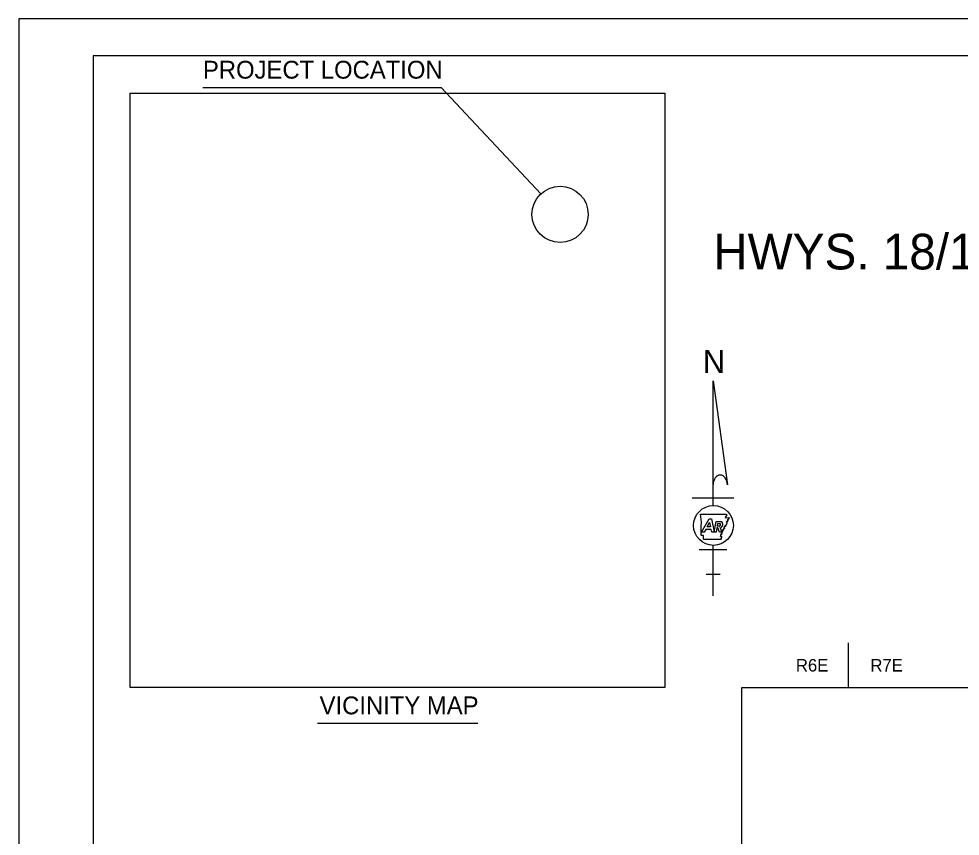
# Model space of a CAD drawing. Extents: x -0.54 to 1.64, y 0 to 0.92.
# Drawn here: x 0 to 0.528, y 0.458 to 0.917 of the extents above; entities that cross this region are included whole.
import ezdxf

# ---------------------------------------------------------------- set-up
doc = ezdxf.new("R2010")
doc.units = 0
for name, color, linetype in [('DSN_DRFT_Border', 7, 'Continuous'), ('DSN_DRFT_DNC', 7, 'Continuous'), ('SHET_Annotations', 7, 'Continuous'), ('SHET_Border-Lines', 7, 'Continuous'), ('SHET_Border-Text', 7, 'Continuous')]:
    doc.layers.add(name, color=color, linetype=linetype)

msp = doc.modelspace()

# ---------------------------------------------------------------- linework, layer by layer
at = {"layer": 'DSN_DRFT_Border'}
msp.add_circle((0.30365181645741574, 0.8070224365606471), 0.015780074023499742, dxfattribs=at)
at = {"layer": 'DSN_DRFT_DNC'}
for points in [[(0.06250000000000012, 0.8750000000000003), (0.3625000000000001, 0.8750000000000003), (0.3625000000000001, 0.541666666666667), (0.06250000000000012, 0.541666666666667)], [(0.4056037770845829, 0.541666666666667), (1.052729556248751, 0.541666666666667), (1.052729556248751, 0.14429633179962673), (0.4056037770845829, 0.14429633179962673)]]:
    msp.add_lwpolyline(points, close=True, dxfattribs=at)
at = {"layer": 'SHET_Annotations'}
for p, q in [((0.38948951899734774, 0.7135952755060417), (0.39754834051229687, 0.6553494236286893)), ((0.38948951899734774, 0.6437483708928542), (0.38948951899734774, 0.7135952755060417)), ((0.3778235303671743, 0.6480662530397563), (0.4011505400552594, 0.6480662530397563)), ((0.38295909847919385, 0.628768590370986), (0.38726592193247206, 0.636374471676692)), ((0.3861273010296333, 0.6317539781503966), (0.3875359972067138, 0.6342417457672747)), ((0.38726592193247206, 0.636374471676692), (0.3885457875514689, 0.636374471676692)), ((0.39114354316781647, 0.6347879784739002), (0.3941343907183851, 0.6347879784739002)), ((0.39207574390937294, 0.6337144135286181), (0.3934801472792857, 0.6337144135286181)), ((0.3844368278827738, 0.628768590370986), (0.38295909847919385, 0.628768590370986)), ((0.3853405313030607, 0.6303645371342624), (0.3844368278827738, 0.628768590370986)), ((0.3883657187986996, 0.6303645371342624), (0.3853405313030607, 0.6303645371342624)), ((0.3880683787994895, 0.6317539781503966), (0.3861273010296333, 0.6317539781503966)), ((0.39121379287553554, 0.628768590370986), (0.3887072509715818, 0.628768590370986)), ((0.39215362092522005, 0.6311875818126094), (0.39163537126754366, 0.6311875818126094)), ((0.39307542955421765, 0.6320901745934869), (0.3917926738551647, 0.6320901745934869)), ((0.39304735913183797, 0.628768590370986), (0.39215362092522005, 0.6311875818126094)), ((0.3943611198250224, 0.628768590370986), (0.39304735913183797, 0.628768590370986)), ((0.39341970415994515, 0.6313166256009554), (0.3943611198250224, 0.628768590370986)), ((0.3934437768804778, 0.6312514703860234), (0.3935375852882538, 0.6313452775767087)), ((0.38171313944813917, 0.6189956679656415), (0.3972644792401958, 0.6189956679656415)), ((0.38948951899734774, 0.5930567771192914), (0.38948951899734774, 0.6214049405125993)), ((0.38559955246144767, 0.6051854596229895), (0.39337664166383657, 0.6051854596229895)), ((0.46523779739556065, 0.5666666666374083), (0.46523900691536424, 0.541666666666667))]:
    msp.add_line(p, q, dxfattribs=at)
for points in [[(0.3823997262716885, 0.6388386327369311), (0.38665906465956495, 0.6388382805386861), (0.39039929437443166, 0.6388464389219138), (0.3948076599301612, 0.6389138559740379), (0.39685146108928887, 0.6389621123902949)], [(0.38287129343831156, 0.6322193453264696), (0.38294544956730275, 0.6344632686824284), (0.3823997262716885, 0.6388386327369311)], [(0.3875359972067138, 0.6342417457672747), (0.3880683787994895, 0.6317539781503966)], [(0.3885457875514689, 0.636374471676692), (0.39012993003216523, 0.6289719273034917), (0.39114354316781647, 0.6347879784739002)], [(0.3917926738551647, 0.6320901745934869), (0.39207574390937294, 0.6337144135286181)], [(0.39621951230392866, 0.6369062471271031), (0.3982182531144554, 0.6370070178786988)], [(0.38270949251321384, 0.6273159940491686), (0.38287129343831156, 0.6322193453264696)], [(0.3887072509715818, 0.628768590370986), (0.3883657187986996, 0.6303645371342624)], [(0.39163537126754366, 0.6311875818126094), (0.39121379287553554, 0.628768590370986)], [(0.39382408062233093, 0.6247445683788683), (0.3841706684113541, 0.6247616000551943), (0.3841664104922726, 0.6268930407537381)]]:
    msp.add_lwpolyline(points, dxfattribs=at)
for centre, major_axis, ratio, start_param, end_param in [((0.39351564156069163, 0.6552233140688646), (-0.0001723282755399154, 0.005599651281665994), 0.719777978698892, 4.712385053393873, 7.768525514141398), ((0.39276797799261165, 0.6330293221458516), (-0.0009882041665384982, 3.3077395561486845e-15), 0.9999870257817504, 1.8871691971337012, 3.907620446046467), ((0.39302248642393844, 0.6332076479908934), (-0.0019323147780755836, 4.023961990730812e-15), 0.9999870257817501, 1.7778380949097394, 4.099263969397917)]:
    msp.add_ellipse(centre, major_axis=major_axis, ratio=ratio, start_param=start_param, end_param=end_param, dxfattribs=at)
msp.add_ellipse((0.3896705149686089, 0.6325765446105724), major_axis=(0.0111735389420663, 0), ratio=0.9999755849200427, dxfattribs=at)
for points in [[(0.3971853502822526, 0.6344700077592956), (0.3971974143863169, 0.6343951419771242), (0.3971523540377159, 0.6343138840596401), (0.3971349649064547, 0.634232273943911), (0.3971409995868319, 0.6341492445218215), (0.39705797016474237, 0.6341048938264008), (0.39698558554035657, 0.6340516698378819), (0.397029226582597, 0.6339885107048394), (0.3971087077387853, 0.633931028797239), (0.3971853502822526, 0.6338873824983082), (0.39723431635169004, 0.6338412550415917), (0.39724815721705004, 0.6337348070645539), (0.39726199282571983, 0.6336649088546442), (0.39728966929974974, 0.6335694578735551), (0.39729889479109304, 0.6335041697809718), (0.39725205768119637, 0.633425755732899), (0.3971974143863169, 0.6334090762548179), (0.39713745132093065, 0.6334268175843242), (0.3970703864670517, 0.6334324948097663), (0.3970153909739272, 0.6333821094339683), (0.39697529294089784, 0.6333065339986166), (0.396936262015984, 0.6332327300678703), (0.3969050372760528, 0.6331699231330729), (0.3968762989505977, 0.6331014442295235), (0.3968202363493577, 0.6330216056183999), (0.39674891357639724, 0.6330095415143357), (0.3966644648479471, 0.6329875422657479), (0.3966137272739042, 0.6329304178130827), (0.39662330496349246, 0.6328324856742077), (0.3966704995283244, 0.6327675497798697), (0.39670633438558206, 0.6326859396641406), (0.39673223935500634, 0.6326146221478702), (0.3967205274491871, 0.6325248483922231), (0.3966836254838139, 0.6324577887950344), (0.396636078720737, 0.6324184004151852), (0.3966137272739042, 0.6323353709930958), (0.3965793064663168, 0.6322704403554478), (0.396548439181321, 0.6322495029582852), (0.39648528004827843, 0.6322555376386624), (0.39641644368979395, 0.6322683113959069), (0.3963589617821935, 0.6322633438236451), (0.3963046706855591, 0.6322353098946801), (0.3962478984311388, 0.6322526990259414), (0.39619006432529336, 0.6323169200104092), (0.3961418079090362, 0.632364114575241), (0.39608858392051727, 0.6323818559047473), (0.39603394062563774, 0.632353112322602), (0.39602542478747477, 0.6322654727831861), (0.39605168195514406, 0.6321764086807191), (0.3960743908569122, 0.6320561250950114), (0.39605168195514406, 0.6319823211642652), (0.3960424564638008, 0.6318599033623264)], [(0.39685146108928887, 0.6389621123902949), (0.3968645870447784, 0.6388464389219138), (0.396900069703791, 0.6387864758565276), (0.3969050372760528, 0.6386743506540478), (0.39695152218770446, 0.6386264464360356), (0.397029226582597, 0.6385796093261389), (0.39709451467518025, 0.638504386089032), (0.3971119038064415, 0.6384156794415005), (0.3970902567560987, 0.6383230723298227), (0.397085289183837, 0.63821768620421), (0.3970757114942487, 0.638128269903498), (0.39705797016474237, 0.6380487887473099), (0.39699623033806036, 0.6379817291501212), (0.396936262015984, 0.6379352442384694), (0.39688090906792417, 0.6378813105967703), (0.39684116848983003, 0.6378209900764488), (0.3967733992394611, 0.6377592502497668), (0.3967038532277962, 0.6376918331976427), (0.3966463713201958, 0.6376350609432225), (0.3965924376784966, 0.6375609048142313), (0.39656582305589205, 0.6374800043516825), (0.396506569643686, 0.6374211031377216), (0.39645831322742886, 0.6373678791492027), (0.3963955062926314, 0.637296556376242), (0.39636463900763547, 0.6372270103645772), (0.3963046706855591, 0.6371446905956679), (0.39629012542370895, 0.6370666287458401), (0.39625144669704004, 0.6370034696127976), (0.3962478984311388, 0.6369917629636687)], [(0.39818950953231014, 0.6370055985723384), (0.3982182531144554, 0.6370070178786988), (0.398307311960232, 0.6369137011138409), (0.39834670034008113, 0.636833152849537), (0.39840595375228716, 0.6367895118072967), (0.39847230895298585, 0.6367660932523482), (0.39852162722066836, 0.6367050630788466), (0.39855533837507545, 0.6366383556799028), (0.3985375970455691, 0.6365801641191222), (0.39846272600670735, 0.6365751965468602), (0.3983811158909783, 0.6365624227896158), (0.39830270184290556, 0.6365652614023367), (0.39823812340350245, 0.6365106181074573), (0.39829737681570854, 0.6364414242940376), (0.39837401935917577, 0.6363740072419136), (0.3983953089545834, 0.6363037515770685), (0.3983527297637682, 0.6362366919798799), (0.3982679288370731, 0.6361987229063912), (0.3981863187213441, 0.6361657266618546), (0.39811286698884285, 0.6361043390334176), (0.3980773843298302, 0.6360429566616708), (0.39799684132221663, 0.6360170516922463), (0.3979131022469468, 0.635992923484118), (0.3978392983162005, 0.6359854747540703), (0.39775520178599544, 0.6359687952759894), (0.39767394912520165, 0.6359290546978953), (0.3976395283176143, 0.6358616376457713), (0.39764982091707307, 0.6357651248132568), (0.39764733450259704, 0.6356618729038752), (0.3977328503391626, 0.635627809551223), (0.39780949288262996, 0.6356239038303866), (0.3978850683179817, 0.6355862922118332), (0.3978754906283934, 0.6355277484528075), (0.39782084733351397, 0.6354528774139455), (0.39775520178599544, 0.6353953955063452), (0.3976895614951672, 0.635367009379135), (0.39762853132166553, 0.6353105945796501), (0.39764982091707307, 0.6352545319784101), (0.39770481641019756, 0.6352201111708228), (0.3977442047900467, 0.6351587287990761), (0.3977385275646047, 0.6351037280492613), (0.3976757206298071, 0.6350639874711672), (0.3976068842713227, 0.635079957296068), (0.3975557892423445, 0.6351459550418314), (0.3974997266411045, 0.6351654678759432), (0.39744827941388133, 0.6351899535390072), (0.3973911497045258, 0.6351565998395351), (0.3973911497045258, 0.635079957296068), (0.3973705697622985, 0.6349986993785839), (0.39738866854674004, 0.6349380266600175), (0.3974103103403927, 0.6348535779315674), (0.3974085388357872, 0.6347904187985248), (0.39738866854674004, 0.6346995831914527), (0.39734289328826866, 0.6346069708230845), (0.39729286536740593, 0.6345792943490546), (0.3972680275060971, 0.6346790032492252), (0.3972598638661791, 0.6347602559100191), (0.39722686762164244, 0.6348088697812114), (0.3971853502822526, 0.634810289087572), (0.3971299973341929, 0.6347719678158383), (0.3970703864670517, 0.6347102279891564), (0.3969944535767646, 0.6346442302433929), (0.3969490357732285, 0.6345792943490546), (0.396973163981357, 0.6344980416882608), (0.39702993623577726, 0.6344774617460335), (0.3970757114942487, 0.6344912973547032), (0.39709913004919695, 0.6345448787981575), (0.3971409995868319, 0.6345516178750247), (0.3971853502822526, 0.6344700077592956)], [(0.3945823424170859, 0.6293661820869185), (0.3945752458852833, 0.6293633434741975), (0.39452840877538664, 0.6293037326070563), (0.39455431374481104, 0.6292104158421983), (0.3946572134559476, 0.6291742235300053), (0.39470440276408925, 0.6290851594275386), (0.39470653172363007, 0.6290063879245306), (0.39467353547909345, 0.6288978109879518), (0.3946252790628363, 0.6288467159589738), (0.39453373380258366, 0.6288254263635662), (0.39446312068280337, 0.6288130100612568), (0.3944528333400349, 0.6286920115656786), (0.39441983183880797, 0.628631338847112), (0.3943651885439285, 0.6286132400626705), (0.3942857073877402, 0.6286522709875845), (0.39423780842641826, 0.6286724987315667), (0.39418032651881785, 0.6286983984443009), (0.3941065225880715, 0.6287402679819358), (0.3940501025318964, 0.6287331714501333), (0.39406642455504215, 0.6286182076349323), (0.3940717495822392, 0.6286132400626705), (0.39413561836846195, 0.6285259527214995), (0.3941973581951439, 0.6284571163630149), (0.39422680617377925, 0.628375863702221)], [(0.3945823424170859, 0.6293661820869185), (0.3945752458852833, 0.6293633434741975), (0.39452840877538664, 0.6293037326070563), (0.39455431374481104, 0.6292104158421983), (0.3946572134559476, 0.6291742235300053), (0.39470440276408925, 0.6290851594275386), (0.39470653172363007, 0.6290063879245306), (0.39467353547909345, 0.6288978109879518), (0.3946252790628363, 0.6288467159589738), (0.39453373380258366, 0.6288254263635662), (0.39446312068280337, 0.6288130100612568), (0.3944528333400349, 0.6286920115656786), (0.39441983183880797, 0.628631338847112), (0.3943651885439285, 0.6286132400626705), (0.3942857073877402, 0.6286522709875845), (0.39423780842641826, 0.6286724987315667), (0.39418032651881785, 0.6286983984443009), (0.3941065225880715, 0.6287402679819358), (0.3940501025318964, 0.6287331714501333), (0.39406642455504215, 0.6286182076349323), (0.3940717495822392, 0.6286132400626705), (0.39413561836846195, 0.6285259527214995), (0.3941973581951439, 0.6284571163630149), (0.39422680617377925, 0.628375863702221)], [(0.3960424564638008, 0.6318599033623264), (0.3959509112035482, 0.6317903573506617), (0.3959090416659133, 0.6317172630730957), (0.3956748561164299, 0.6317385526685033), (0.3956812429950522, 0.6316562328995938), (0.3955978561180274, 0.6316129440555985), (0.3955236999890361, 0.6315593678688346), (0.395565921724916, 0.6314954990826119), (0.39564540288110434, 0.6314380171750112), (0.39572453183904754, 0.6313936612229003), (0.39577385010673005, 0.6313493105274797), (0.39578662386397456, 0.6312393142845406), (0.39580117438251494, 0.6311718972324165), (0.395827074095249, 0.6310757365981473), (0.39583736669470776, 0.6310115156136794), (0.39578981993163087, 0.6309334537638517), (0.3957341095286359, 0.6309167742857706), (0.3956773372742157, 0.6309355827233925), (0.3956088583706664, 0.630940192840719), (0.3955538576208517, 0.6308887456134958), (0.39551376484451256, 0.6308142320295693), (0.3954750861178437, 0.6307390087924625), (0.3954449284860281, 0.6306769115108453), (0.3954140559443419, 0.6306077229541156), (0.39535870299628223, 0.6305278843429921), (0.39528844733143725, 0.630516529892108), (0.39520328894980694, 0.6304952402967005), (0.39515290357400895, 0.6304384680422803), (0.395161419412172, 0.6303398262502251), (0.39520861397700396, 0.630274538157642), (0.3952451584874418, 0.6301918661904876), (0.39527035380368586, 0.6301212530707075), (0.39525970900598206, 0.6300321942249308), (0.395222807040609, 0.6299647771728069), (0.39517455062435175, 0.6299250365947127), (0.39515290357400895, 0.6298420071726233), (0.39511813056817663, 0.6297774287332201), (0.39508726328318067, 0.6297579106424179), (0.39502445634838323, 0.6297642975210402), (0.3949563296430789, 0.6297763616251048), (0.3948981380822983, 0.629771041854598), (0.39484349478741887, 0.6297419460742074), (0.3947867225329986, 0.629760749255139), (0.3947288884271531, 0.6298231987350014), (0.39468134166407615, 0.6298711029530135), (0.3946284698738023, 0.6298899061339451), (0.3945720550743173, 0.6298611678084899), (0.39456389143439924, 0.6297728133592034), (0.3945905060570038, 0.6296848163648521), (0.3946135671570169, 0.6295624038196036), (0.3945905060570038, 0.6294900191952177), (0.3945823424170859, 0.6293661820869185)], [(0.3841664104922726, 0.6268930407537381), (0.3841766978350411, 0.6268877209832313), (0.38412666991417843, 0.6269217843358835), (0.38405747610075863, 0.6269554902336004), (0.3839801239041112, 0.6269604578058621), (0.38388254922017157, 0.6269735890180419), (0.3838012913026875, 0.6269813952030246), (0.38371826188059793, 0.6270374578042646), (0.38362920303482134, 0.6269806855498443), (0.3835284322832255, 0.6269370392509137), (0.38346988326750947, 0.6269860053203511), (0.38339466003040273, 0.6269526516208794), (0.3833407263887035, 0.6269703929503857), (0.38324918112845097, 0.6269054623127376), (0.3831608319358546, 0.6269295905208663), (0.3830990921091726, 0.62691184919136), (0.3830203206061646, 0.6269136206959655), (0.3830039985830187, 0.6270037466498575), (0.3829266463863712, 0.6270158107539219), (0.3828610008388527, 0.6270534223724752), (0.38281700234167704, 0.6271446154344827), (0.38278435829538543, 0.6272177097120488), (0.38270949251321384, 0.6273159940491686)], [(0.39422680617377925, 0.628375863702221), (0.3942019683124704, 0.6283144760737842), (0.39417145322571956, 0.6282094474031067), (0.39418032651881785, 0.6281207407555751), (0.39422077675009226, 0.6280448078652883), (0.39428251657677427, 0.6280022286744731), (0.3943527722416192, 0.6279419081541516), (0.394346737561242, 0.6278485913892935), (0.39430628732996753, 0.6278155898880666), (0.3942129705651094, 0.6278372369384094), (0.3941423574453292, 0.6278709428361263), (0.394082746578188, 0.6278517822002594), (0.39400255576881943, 0.6278127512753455), (0.3939408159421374, 0.6278021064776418), (0.3939433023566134, 0.6276768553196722), (0.394023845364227, 0.6275877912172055), (0.3940948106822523, 0.6275877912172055), (0.3941785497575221, 0.6275775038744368), (0.3942069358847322, 0.627482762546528), (0.39415867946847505, 0.6274025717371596), (0.3940806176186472, 0.6273642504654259), (0.39398020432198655, 0.6274125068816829), (0.3939095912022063, 0.6274621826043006), (0.39383827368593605, 0.6275090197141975), (0.3937492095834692, 0.6275324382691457), (0.393697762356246, 0.6275228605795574), (0.3936743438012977, 0.6274125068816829), (0.39371656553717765, 0.6273120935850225), (0.39378434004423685, 0.6272421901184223), (0.3938474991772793, 0.627153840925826), (0.39383827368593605, 0.6270864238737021), (0.3937907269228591, 0.6270693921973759), (0.39370592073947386, 0.6270502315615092), (0.39365624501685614, 0.6270250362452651), (0.3936438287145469, 0.6270037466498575), (0.3936697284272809, 0.6269136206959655), (0.39369243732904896, 0.6268171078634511), (0.39369243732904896, 0.6267415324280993), (0.39366369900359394, 0.6266755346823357), (0.393618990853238, 0.6265705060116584), (0.39362431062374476, 0.6265020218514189), (0.39365624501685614, 0.6264686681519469), (0.39369527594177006, 0.6264789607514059), (0.3937492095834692, 0.6265155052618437), (0.39378292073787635, 0.626558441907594), (0.3938123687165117, 0.6266113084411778), (0.3938663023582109, 0.6266553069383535), (0.3939344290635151, 0.6266159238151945), (0.393950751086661, 0.6265343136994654), (0.393911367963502, 0.6264640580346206), (0.3938556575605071, 0.6264307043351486), (0.39378859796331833, 0.6264044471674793), (0.39373785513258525, 0.6263476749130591), (0.3937499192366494, 0.6262777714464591), (0.3937907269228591, 0.6262415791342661), (0.393889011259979, 0.626260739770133), (0.39395288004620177, 0.6262901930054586), (0.3939915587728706, 0.6263246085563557), (0.39403555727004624, 0.6263703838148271), (0.3940579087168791, 0.6264168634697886), (0.3940933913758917, 0.6264640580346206), (0.3941551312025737, 0.626476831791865), (0.39418351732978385, 0.6264381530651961), (0.39417145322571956, 0.6263476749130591), (0.39413561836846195, 0.6262621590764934), (0.39408452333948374, 0.6261922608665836), (0.3940302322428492, 0.6261429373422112), (0.3939613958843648, 0.6260343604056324), (0.3939752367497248, 0.625934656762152), (0.39400255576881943, 0.6258505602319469), (0.39403661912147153, 0.6257891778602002), (0.39410119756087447, 0.6258015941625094), (0.39417145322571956, 0.6258101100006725), (0.3942129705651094, 0.6257760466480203), (0.39420942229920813, 0.6257018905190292), (0.3941572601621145, 0.6256291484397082), (0.3941065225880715, 0.6255620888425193), (0.3940806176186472, 0.625468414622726), (0.394091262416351, 0.6254006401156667), (0.394091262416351, 0.625342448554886), (0.39406997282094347, 0.6252743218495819), (0.39403342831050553, 0.625238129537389), (0.3939344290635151, 0.6252391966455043), (0.393832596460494, 0.6252505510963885), (0.3937779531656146, 0.6252196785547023), (0.39378859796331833, 0.6251306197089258), (0.3938474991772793, 0.625064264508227), (0.3938897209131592, 0.6250305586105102), (0.393950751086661, 0.6249563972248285), (0.3939770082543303, 0.6248960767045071), (0.39396955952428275, 0.6248432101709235), (0.39393123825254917, 0.6247963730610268), (0.39382408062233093, 0.6247445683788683)], [(0.39422680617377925, 0.628375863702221), (0.3942019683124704, 0.6283144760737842), (0.39417145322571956, 0.6282094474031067), (0.39418032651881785, 0.6281207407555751), (0.39422077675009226, 0.6280448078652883), (0.39428251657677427, 0.6280022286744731), (0.3943527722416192, 0.6279419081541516), (0.394346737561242, 0.6278485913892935), (0.39430628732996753, 0.6278155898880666), (0.3942129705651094, 0.6278372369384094), (0.3941423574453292, 0.6278709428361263), (0.394082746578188, 0.6278517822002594), (0.39400255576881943, 0.6278127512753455), (0.3939408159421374, 0.6278021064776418), (0.3939433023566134, 0.6276768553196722), (0.394023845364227, 0.6275877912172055), (0.3940948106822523, 0.6275877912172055), (0.3941785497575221, 0.6275775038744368), (0.3942069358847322, 0.627482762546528), (0.39415867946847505, 0.6274025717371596), (0.3940806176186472, 0.6273642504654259), (0.39398020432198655, 0.6274125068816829), (0.3939095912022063, 0.6274621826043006), (0.39383827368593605, 0.6275090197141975), (0.3937492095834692, 0.6275324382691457), (0.393697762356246, 0.6275228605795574), (0.3936743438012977, 0.6274125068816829), (0.39371656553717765, 0.6273120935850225), (0.39378434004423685, 0.6272421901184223), (0.3938474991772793, 0.627153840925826), (0.39383827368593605, 0.6270864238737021), (0.3937907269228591, 0.6270693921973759), (0.39370592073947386, 0.6270502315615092), (0.39365624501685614, 0.6270250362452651), (0.3936438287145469, 0.6270037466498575), (0.3936697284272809, 0.6269136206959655), (0.39369243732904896, 0.6268171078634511), (0.39369243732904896, 0.6267415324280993), (0.39366369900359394, 0.6266755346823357), (0.393618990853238, 0.6265705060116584), (0.39362431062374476, 0.6265020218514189), (0.39365624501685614, 0.6264686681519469), (0.39369527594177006, 0.6264789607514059), (0.3937492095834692, 0.6265155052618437), (0.39378292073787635, 0.626558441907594), (0.3938123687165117, 0.6266113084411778), (0.3938663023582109, 0.6266553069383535), (0.3939344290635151, 0.6266159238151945), (0.393950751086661, 0.6265343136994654), (0.393911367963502, 0.6264640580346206), (0.3938556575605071, 0.6264307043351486), (0.39378859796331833, 0.6264044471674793), (0.39373785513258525, 0.6263476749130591), (0.3937499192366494, 0.6262777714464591), (0.3937907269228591, 0.6262415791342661), (0.393889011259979, 0.626260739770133), (0.39395288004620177, 0.6262901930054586), (0.3939915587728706, 0.6263246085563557), (0.39403555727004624, 0.6263703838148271), (0.3940579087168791, 0.6264168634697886), (0.3940933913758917, 0.6264640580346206), (0.3941551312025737, 0.626476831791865), (0.39418351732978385, 0.6264381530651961), (0.39417145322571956, 0.6263476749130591), (0.39413561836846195, 0.6262621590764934), (0.39408452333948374, 0.6261922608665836), (0.3940302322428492, 0.6261429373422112), (0.3939613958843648, 0.6260343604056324), (0.3939752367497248, 0.625934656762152), (0.39400255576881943, 0.6258505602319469), (0.39403661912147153, 0.6257891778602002), (0.39410119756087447, 0.6258015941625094), (0.39417145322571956, 0.6258101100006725), (0.3942129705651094, 0.6257760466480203), (0.39420942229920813, 0.6257018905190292), (0.3941572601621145, 0.6256291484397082), (0.3941065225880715, 0.6255620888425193), (0.3940806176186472, 0.625468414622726), (0.394091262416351, 0.6254006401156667), (0.394091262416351, 0.625342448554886), (0.39406997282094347, 0.6252743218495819), (0.39403342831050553, 0.625238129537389), (0.3939344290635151, 0.6252391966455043), (0.393832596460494, 0.6252505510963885), (0.3937779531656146, 0.6252196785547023), (0.39378859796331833, 0.6251306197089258), (0.3938474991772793, 0.625064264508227), (0.3938897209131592, 0.6250305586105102), (0.393950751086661, 0.6249563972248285), (0.3939770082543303, 0.6248960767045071), (0.39396955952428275, 0.6248432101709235), (0.39393123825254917, 0.6247963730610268), (0.39382408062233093, 0.6247445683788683)]]:
    msp.add_spline(points, degree=3, dxfattribs=at)
at = {"layer": 'SHET_Border-Lines'}
for points in [[(0, 0), (1.416666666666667, 0), (1.416666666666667, 0.9166666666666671), (0, 0.9166666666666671)], [(0.04166666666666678, 0.02083333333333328), (1.395833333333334, 0.02083333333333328), (1.395833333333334, 0.8958333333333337), (0.04166666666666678, 0.8958333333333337)]]:
    msp.add_lwpolyline(points, close=True, dxfattribs=at)
at = {"layer": 'SHET_Border-Text'}
for p, q in [((0.10328881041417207, 0.8781408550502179), (0.23686414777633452, 0.8781408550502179)), ((0.23686414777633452, 0.8781408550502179), (0.2928493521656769, 0.8185253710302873)), ((0.16750000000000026, 0.521666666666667), (0.25750000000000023, 0.521666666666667))]:
    msp.add_line(p, q, dxfattribs=at)

# ---------------------------------------------------------------- texts
at = {"layer": 'SHET_Annotations'}
for s, height, p in [('PROJECT LOCATION', 0.01, (0.10328881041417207, 0.8831408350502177)), ('HWYS. 18/139 INTERS. IMPVTS. (MONETTE) (S)', 0.02, (0.38958832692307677, 0.7761402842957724)), ('N', 0.013, (0.3836936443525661, 0.717990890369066)), ('STS 10-03-17', 0.00032304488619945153, (0.38860159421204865, 0.6214950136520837)), ('R6E', 0.006999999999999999, (0.4359285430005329, 0.5506666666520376)), ('R7E', 0.006999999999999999, (0.4777384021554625, 0.5506666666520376)), ('VICINITY MAP', 0.01, (0.16874295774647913, 0.5266666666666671))]:
    msp.add_text(s, height=height, dxfattribs=at).set_placement(p)

doc.saveas('drawing.dxf')
